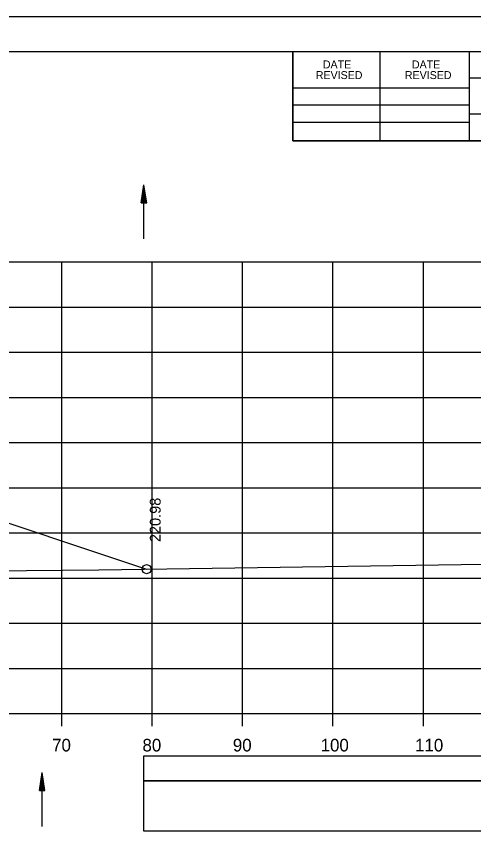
# Model space of a CAD drawing. Extents: x 1386544 to 1388153, y 379785 to 390999.
# Drawn here: x 1387424.6 to 1387475.2, y 389628.1 to 389718.9 of the extents above; entities that cross this region are included whole.
import ezdxf

# ---------------------------------------------------------------- set-up
doc = ezdxf.new("R2010")
doc.units = 0
for name, color, linetype in [('R_Axis', 7, 'Continuous'), ('R_Axis Annot', 7, 'Continuous'), ('R_Border', 7, 'Continuous'), ('R_Exist Surface', 7, 'Continuous'), ('R_Fin Surface', 7, 'Continuous'), ('R_Grid', 7, 'Continuous'), ('R_No Plot', 7, 'Continuous'), ('R_Water', 7, 'Continuous'), ('R_Xsect Elev', 7, 'Continuous')]:
    doc.layers.add(name, color=color, linetype=linetype)

msp = doc.modelspace()

# ---------------------------------------------------------------- linework, layer by layer
at = {"layer": 'R_Axis'}
for p, q in [((1387209.676, 389641.723), (1387509.676, 389641.723)), ((1387429.676, 389640.323), (1387429.676, 389641.723)), ((1387439.676, 389640.323), (1387439.676, 389641.723)), ((1387449.676, 389640.323), (1387449.676, 389641.723)), ((1387459.676, 389640.323), (1387459.676, 389641.723)), ((1387469.676, 389640.323), (1387469.676, 389641.723))]:
    msp.add_line(p, q, dxfattribs=at)
at = {"layer": 'R_Axis Annot'}
for points in [[(1387438.697, 389634.279), (1387509.676, 389634.279), (1387509.676, 389636.988), (1387438.697, 389636.988)], [(1387438.697, 389628.752), (1387509.676, 389628.752), (1387509.676, 389634.279), (1387438.697, 389634.279)]]:
    msp.add_lwpolyline(points, close=True, dxfattribs=at)
at = {"layer": 'R_Border'}
for p, q in [((1387201.676, 389715.017), (1387517.856, 389715.017)), ((1387455.216, 389705.137), (1387455.216, 389715.017)), ((1387464.896, 389705.137), (1387464.896, 389715.017)), ((1387474.756, 389715.017), (1387474.756, 389705.137)), ((1387517.856, 389712.077), (1387474.756, 389712.077)), ((1387455.216, 389710.997), (1387474.756, 389710.997)), ((1387455.216, 389709.137), (1387474.756, 389709.137)), ((1387517.856, 389708.077), (1387474.756, 389708.077)), ((1387455.216, 389707.197), (1387474.756, 389707.197)), ((1387517.856, 389705.137), (1387455.216, 389705.137))]:
    msp.add_line(p, q, dxfattribs=at)
at = {"layer": 'R_Exist Surface'}
msp.add_lwpolyline([(1387209.676, 389655.861), (1387214.678, 389655.888), (1387219.166, 389655.957), (1387237.542, 389656.059), (1387242.612, 389656.141), (1387248.797, 389656.208), (1387262.733, 389656.368), (1387273.813, 389656.485), (1387281.634, 389656.574), (1387297.313, 389656.692), (1387306.167, 389656.702), (1387328.441, 389656.727), (1387356.889, 389657.011), (1387379.375, 389657.151), (1387405.721, 389657.387), (1387433.772, 389657.631), (1387476.379, 389658.253), (1387486.619, 389658.402), (1387491.09, 389658.469), (1387509.676, 389658.748)], dxfattribs=at)
at = {"layer": 'R_Fin Surface'}
msp.add_lwpolyline([(1387270.773, 389656.453), (1387323.676, 389674.087), (1387329.508, 389675.059), (1387339.676, 389676.754), (1387345.676, 389676.466), (1387347.676, 389676.37), (1387359.676, 389675.794), (1387371.676, 389675.218), (1387373.676, 389675.122), (1387379.676, 389674.834), (1387388.805, 389673.312), (1387395.676, 389672.167), (1387439.055, 389657.708)], dxfattribs=at)
at = {"layer": 'R_Grid'}
for p, q in [((1387209.676, 389691.723), (1387509.676, 389691.723)), ((1387429.676, 389641.723), (1387429.676, 389691.723)), ((1387439.676, 389641.723), (1387439.676, 389691.723)), ((1387449.676, 389641.723), (1387449.676, 389691.723)), ((1387459.676, 389641.723), (1387459.676, 389691.723)), ((1387469.676, 389641.723), (1387469.676, 389691.723)), ((1387209.676, 389686.723), (1387509.676, 389686.723)), ((1387209.676, 389681.723), (1387509.676, 389681.723)), ((1387209.676, 389676.723), (1387509.676, 389676.723)), ((1387209.676, 389671.723), (1387509.676, 389671.723)), ((1387209.676, 389666.723), (1387509.676, 389666.723)), ((1387209.676, 389661.723), (1387509.676, 389661.723)), ((1387209.676, 389656.723), (1387509.676, 389656.723)), ((1387209.676, 389651.723), (1387509.676, 389651.723)), ((1387209.676, 389646.723), (1387509.676, 389646.723)), ((1387209.676, 389641.723), (1387509.676, 389641.723))]:
    msp.add_line(p, q, dxfattribs=at)
at = {"layer": 'R_No Plot'}
msp.add_line((1387189.275, 389718.911), (1387522.609, 389718.911), dxfattribs=at)
for points in [[(1387189.269, 389718.911), (1387522.609, 389718.911), (1387522.609, 389505.574), (1387189.269, 389505.574)], [(1387435.596, 389715.017), (1387455.216, 389715.017), (1387455.216, 389705.137), (1387471.328, 389705.137), (1387494.528, 389705.137), (1387494.528, 389680.804), (1387517.856, 389680.804), (1387517.856, 389509.557), (1387201.676, 389509.557), (1387201.676, 389715.017)]]:
    msp.add_lwpolyline(points, close=True, dxfattribs=at)
msp.add_circle((1387439.055, 389657.708), 0.5, dxfattribs=at)
at = {"layer": 'R_Water'}
for p, q in [((1387438.457, 389698.281), (1387438.757, 389700.281)), ((1387438.457, 389698.281), (1387438.757, 389700.281)), ((1387438.507, 389698.281), (1387438.757, 389699.947)), ((1387438.507, 389698.281), (1387438.757, 389699.947)), ((1387438.558, 389698.281), (1387438.757, 389699.603)), ((1387438.558, 389698.281), (1387438.757, 389699.603)), ((1387438.757, 389694.281), (1387438.757, 389700.281)), ((1387439.057, 389698.281), (1387438.757, 389700.281)), ((1387439.057, 389698.281), (1387438.757, 389700.281)), ((1387439.007, 389698.281), (1387438.757, 389699.947)), ((1387439.007, 389698.281), (1387438.757, 389699.947)), ((1387438.956, 389698.281), (1387438.757, 389699.603)), ((1387438.956, 389698.281), (1387438.757, 389699.603)), ((1387438.608, 389698.281), (1387438.757, 389699.27)), ((1387438.608, 389698.281), (1387438.757, 389699.27)), ((1387438.66, 389698.281), (1387438.757, 389698.931)), ((1387438.66, 389698.281), (1387438.757, 389698.931)), ((1387438.906, 389698.281), (1387438.757, 389699.27)), ((1387438.906, 389698.281), (1387438.757, 389699.27)), ((1387438.855, 389698.281), (1387438.757, 389698.931)), ((1387438.855, 389698.281), (1387438.757, 389698.931)), ((1387438.457, 389698.281), (1387439.057, 389698.281)), ((1387438.457, 389698.281), (1387439.057, 389698.281)), ((1387438.71, 389698.281), (1387438.757, 389698.597)), ((1387438.71, 389698.281), (1387438.757, 389698.597)), ((1387438.804, 389698.281), (1387438.757, 389698.597)), ((1387438.804, 389698.281), (1387438.757, 389698.597)), ((1387427.199, 389633.213), (1387427.499, 389635.213)), ((1387427.199, 389633.213), (1387427.499, 389635.213)), ((1387427.499, 389629.213), (1387427.499, 389635.213)), ((1387427.799, 389633.213), (1387427.499, 389635.213)), ((1387427.799, 389633.213), (1387427.499, 389635.213)), ((1387427.249, 389633.213), (1387427.499, 389634.879)), ((1387427.249, 389633.213), (1387427.499, 389634.879)), ((1387427.3, 389633.213), (1387427.499, 389634.535)), ((1387427.3, 389633.213), (1387427.499, 389634.535)), ((1387427.35, 389633.213), (1387427.499, 389634.202)), ((1387427.35, 389633.213), (1387427.499, 389634.202)), ((1387427.749, 389633.213), (1387427.499, 389634.879)), ((1387427.749, 389633.213), (1387427.499, 389634.879)), ((1387427.698, 389633.213), (1387427.499, 389634.535)), ((1387427.698, 389633.213), (1387427.499, 389634.535)), ((1387427.648, 389633.213), (1387427.499, 389634.202)), ((1387427.648, 389633.213), (1387427.499, 389634.202)), ((1387427.402, 389633.213), (1387427.499, 389633.863)), ((1387427.402, 389633.213), (1387427.499, 389633.863)), ((1387427.452, 389633.213), (1387427.499, 389633.529)), ((1387427.452, 389633.213), (1387427.499, 389633.529)), ((1387427.597, 389633.213), (1387427.499, 389633.863)), ((1387427.597, 389633.213), (1387427.499, 389633.863)), ((1387427.546, 389633.213), (1387427.499, 389633.529)), ((1387427.546, 389633.213), (1387427.499, 389633.529)), ((1387427.199, 389633.213), (1387427.799, 389633.213)), ((1387427.199, 389633.213), (1387427.799, 389633.213))]:
    msp.add_line(p, q, dxfattribs=at)

# ---------------------------------------------------------------- texts
at = {"layer": 'R_Axis Annot'}
for s, p in [('70', (1387428.59, 389637.523)), ('80', (1387438.59, 389637.523)), ('90', (1387448.59, 389637.523)), ('100', (1387458.304, 389637.523)), ('110', (1387468.756, 389637.523))]:
    msp.add_text(s, height=1.4, dxfattribs=at).set_placement(p)
at = {"layer": 'R_Border'}
for s, p in [('DATE', (1387458.554, 389713.153)), ('DATE', (1387468.414, 389713.153)), ('REVISED', (1387457.774, 389711.973)), ('REVISED', (1387467.634, 389711.973))]:
    msp.add_text(s, height=0.8792, rotation=360, dxfattribs=at).set_placement(p)
at = {"layer": 'R_Xsect Elev'}
msp.add_text('220.98', height=1.2, rotation=90, dxfattribs=at).set_placement((1387440.605, 389660.708))

doc.saveas('drawing.dxf')
